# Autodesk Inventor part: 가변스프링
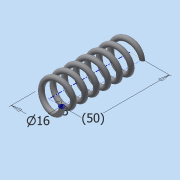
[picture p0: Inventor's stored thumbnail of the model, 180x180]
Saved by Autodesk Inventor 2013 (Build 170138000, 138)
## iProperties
Created: 2019-11
Part Number: 가변스프링
Material: Generic
Document SubType Name: Modeling
Designer: Administrator
Density: 1 g/cm^3
Author: Administrator
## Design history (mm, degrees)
sketch "스케치1"
  geometry: L1 (0, 0)-(8, 0); L2 (8, 0)-(8, 23.5); L3 (8, 23.5)-(0, 23.5); L4 (0, 23.5)-(0, 0); C1 r 1.5 at (8, 0)
  constraints: 8 end point, 2 parallel, 1 centre point, 1 coincident, 1 horizontal, 1 perpendicular
  dimensions: "d0" = 16 diameter of L2 L4; "d2" = 23.5 distance between parallel lines of L1 L3 (derived); "d3" = 3 diameter of C1
feature "코일1" pitch "d4" = 10; turns "d6" = 7; dims "d5" = 23.5 (= d2), "d7" = 0, angle "d8" = 90 deg, angle "d9" = 90 deg, "d10" = 0, "d11" = 0
sketch "스케치2"
  geometry: L1 (-9.5, 0)-(-6.5, 0) reference; 1 further point
  constraints: 1 horizontal alignment
extrude "돌출1" cut sketch "스케치2" stored distance "d12" = 10; taper "d13" = 0 deg
node "작업 평면1"
sketch "스케치3"
  geometry: L1 (1.5, 0)-(-1.5, 0) reference; 1 further point
  constraints: 1 horizontal alignment
extrude "돌출2" cut sketch "스케치3" stored distance "d15" = 10; taper "d16" = 0 deg
node "솔리드1"
node "절단 모서리 투영1"
node "절단 모서리 투영2"
other parameters: "d14" = 90 deg
